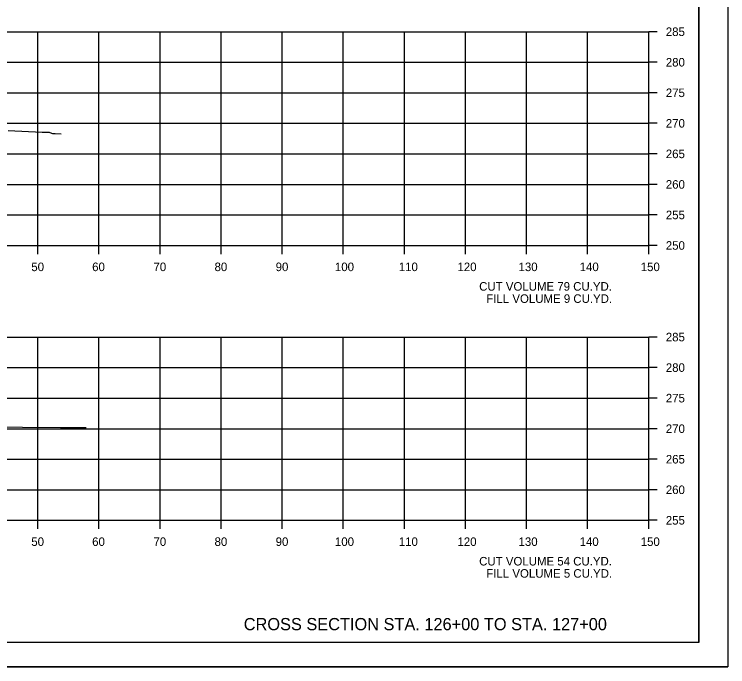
# Model space of a CAD drawing. Extents: x 1103485 to 1107180, y 2010593 to 2011873.
# Drawn here: x 1107063.3 to 1107180.1, y 2010806.2 to 2010913 of the extents above; entities that cross this region are included whole.
import ezdxf

# ---------------------------------------------------------------- set-up
doc = ezdxf.new("R2010")
doc.units = 0
for name, color, linetype in [('R_Axis', 7, 'Continuous'), ('R_Axis Annot', 7, 'Continuous'), ('R_Border', 7, 'Continuous'), ('R_Draft', 7, 'Continuous'), ('R_Exist Surface', 7, 'Continuous'), ('R_Grid', 7, 'Continuous'), ('R_No Plot', 7, 'Continuous')]:
    doc.layers.add(name, color=color, linetype=linetype)

msp = doc.modelspace()

# ---------------------------------------------------------------- linework, layer by layer
at = {"layer": 'R_Axis'}
for p, q in [((1107167.18, 2010875.15), (1107167.18, 2010910.15)), ((1107168.58, 2010910.15), (1107167.18, 2010910.15)), ((1107168.58, 2010905.15), (1107167.18, 2010905.15)), ((1107168.58, 2010900.15), (1107167.18, 2010900.15)), ((1107168.58, 2010895.15), (1107167.18, 2010895.15)), ((1107168.58, 2010890.15), (1107167.18, 2010890.15)), ((1107168.58, 2010885.15), (1107167.18, 2010885.15)), ((1107168.58, 2010880.15), (1107167.18, 2010880.15)), ((1106867.18, 2010875.15), (1107167.18, 2010875.15)), ((1107067.18, 2010873.75), (1107067.18, 2010875.15)), ((1107077.18, 2010873.75), (1107077.18, 2010875.15)), ((1107087.18, 2010873.75), (1107087.18, 2010875.15)), ((1107097.18, 2010873.75), (1107097.18, 2010875.15)), ((1107107.18, 2010873.75), (1107107.18, 2010875.15)), ((1107117.18, 2010873.75), (1107117.18, 2010875.15)), ((1107127.18, 2010873.75), (1107127.18, 2010875.15)), ((1107137.18, 2010873.75), (1107137.18, 2010875.15)), ((1107147.18, 2010873.75), (1107147.18, 2010875.15)), ((1107157.18, 2010873.75), (1107157.18, 2010875.15)), ((1107167.18, 2010873.75), (1107167.18, 2010875.15)), ((1107168.58, 2010875.15), (1107167.18, 2010875.15)), ((1107167.18, 2010830.15), (1107167.18, 2010860.15)), ((1107168.58, 2010860.15), (1107167.18, 2010860.15)), ((1107168.58, 2010855.15), (1107167.18, 2010855.15)), ((1107168.58, 2010850.15), (1107167.18, 2010850.15)), ((1107168.58, 2010845.15), (1107167.18, 2010845.15)), ((1107168.58, 2010840.15), (1107167.18, 2010840.15)), ((1107168.58, 2010835.15), (1107167.18, 2010835.15)), ((1106867.18, 2010830.15), (1107167.18, 2010830.15)), ((1107067.18, 2010828.75), (1107067.18, 2010830.15)), ((1107077.18, 2010828.75), (1107077.18, 2010830.15)), ((1107087.18, 2010828.75), (1107087.18, 2010830.15)), ((1107097.18, 2010828.75), (1107097.18, 2010830.15)), ((1107107.18, 2010828.75), (1107107.18, 2010830.15)), ((1107117.18, 2010828.75), (1107117.18, 2010830.15)), ((1107127.18, 2010828.75), (1107127.18, 2010830.15)), ((1107137.18, 2010828.75), (1107137.18, 2010830.15)), ((1107147.18, 2010828.75), (1107147.18, 2010830.15)), ((1107157.18, 2010828.75), (1107157.18, 2010830.15)), ((1107167.18, 2010828.75), (1107167.18, 2010830.15)), ((1107168.58, 2010830.15), (1107167.18, 2010830.15))]:
    msp.add_line(p, q, dxfattribs=at)
at = {"layer": 'R_Border'}
for q in [(1107175.36, 2011015.61), (1106859.18, 2010810.15)]:
    msp.add_line((1107175.36, 2010810.15), q, dxfattribs=at)
at = {"layer": 'R_Exist Surface'}
for points in [[(1107062.32, 2010893.97), (1107067.87, 2010893.72), (1107069.01, 2010893.69), (1107069.14, 2010893.64), (1107069.56, 2010893.46), (1107070.02, 2010893.51), (1107070.98, 2010893.42)], [(1107052.24, 2010845.53), (1107070.89, 2010845.37), (1107074.81, 2010845.33), (1107075.06, 2010845.32)]]:
    msp.add_lwpolyline(points, dxfattribs=at)
at = {"layer": 'R_Grid'}
for p, q in [((1106867.18, 2010910.15), (1107167.18, 2010910.15)), ((1107067.18, 2010875.15), (1107067.18, 2010910.15)), ((1107077.18, 2010875.15), (1107077.18, 2010910.15)), ((1107087.18, 2010875.15), (1107087.18, 2010910.15)), ((1107097.18, 2010875.15), (1107097.18, 2010910.15)), ((1107107.18, 2010875.15), (1107107.18, 2010910.15)), ((1107117.18, 2010875.15), (1107117.18, 2010910.15)), ((1107127.18, 2010875.15), (1107127.18, 2010910.15)), ((1107137.18, 2010875.15), (1107137.18, 2010910.15)), ((1107147.18, 2010875.15), (1107147.18, 2010910.15)), ((1107157.18, 2010875.15), (1107157.18, 2010910.15)), ((1107167.18, 2010875.15), (1107167.18, 2010910.15)), ((1106867.18, 2010905.15), (1107167.18, 2010905.15)), ((1106867.18, 2010900.15), (1107167.18, 2010900.15)), ((1106867.18, 2010895.15), (1107167.18, 2010895.15)), ((1106867.18, 2010890.15), (1107167.18, 2010890.15)), ((1106867.18, 2010885.15), (1107167.18, 2010885.15)), ((1106867.18, 2010880.15), (1107167.18, 2010880.15)), ((1106867.18, 2010875.15), (1107167.18, 2010875.15)), ((1106867.18, 2010860.15), (1107167.18, 2010860.15)), ((1107067.18, 2010830.15), (1107067.18, 2010860.15)), ((1107077.18, 2010830.15), (1107077.18, 2010860.15)), ((1107087.18, 2010830.15), (1107087.18, 2010860.15)), ((1107097.18, 2010830.15), (1107097.18, 2010860.15)), ((1107107.18, 2010830.15), (1107107.18, 2010860.15)), ((1107117.18, 2010830.15), (1107117.18, 2010860.15)), ((1107127.18, 2010830.15), (1107127.18, 2010860.15)), ((1107137.18, 2010830.15), (1107137.18, 2010860.15)), ((1107147.18, 2010830.15), (1107147.18, 2010860.15)), ((1107157.18, 2010830.15), (1107157.18, 2010860.15)), ((1107167.18, 2010830.15), (1107167.18, 2010860.15)), ((1106867.18, 2010855.15), (1107167.18, 2010855.15)), ((1106867.18, 2010850.15), (1107167.18, 2010850.15)), ((1106867.18, 2010845.15), (1107167.18, 2010845.15)), ((1106867.18, 2010840.15), (1107167.18, 2010840.15)), ((1106867.18, 2010835.15), (1107167.18, 2010835.15)), ((1106867.18, 2010830.15), (1107167.18, 2010830.15))]:
    msp.add_line(p, q, dxfattribs=at)
at = {"layer": 'R_No Plot'}
msp.add_line((1106846.78, 2010806.18), (1107180.12, 2010806.18), dxfattribs=at)
for points in [[(1106846.78, 2011019.51), (1107180.12, 2011019.51), (1107180.12, 2010806.17), (1106846.78, 2010806.17)], [(1107093.1, 2011015.61), (1107093.1, 2011005.73), (1107128.84, 2011005.73), (1107128.84, 2011002.81), (1107152.04, 2011002.81), (1107152.04, 2010978.48), (1107175.36, 2010978.48), (1107175.36, 2010810.15), (1106859.18, 2010810.15), (1106859.18, 2011015.61)]]:
    msp.add_lwpolyline(points, close=True, dxfattribs=at)

# ---------------------------------------------------------------- texts
at = {"layer": 'R_Axis Annot'}
for s, p in [('285', (1107169.98, 2010909.45)), ('280', (1107169.98, 2010904.45)), ('275', (1107169.98, 2010899.45)), ('270', (1107169.98, 2010894.45)), ('265', (1107169.98, 2010889.45)), ('260', (1107169.98, 2010884.45)), ('255', (1107169.98, 2010879.45)), ('250', (1107169.98, 2010874.45)), ('50', (1107066.1, 2010870.95)), ('60', (1107076.06, 2010870.95)), ('70', (1107086.1, 2010870.95)), ('80', (1107096.1, 2010870.95)), ('90', (1107106.1, 2010870.95)), ('100', (1107115.81, 2010870.95)), ('110', (1107126.26, 2010870.95)), ('120', (1107135.87, 2010870.95)), ('130', (1107145.87, 2010870.95)), ('140', (1107155.87, 2010870.95)), ('150', (1107165.87, 2010870.95)), ('CUT VOLUME 79 CU.YD.', (1107139.42, 2010867.75)), ('FILL VOLUME 9 CU.YD.', (1107140.59, 2010865.75)), ('285', (1107169.98, 2010859.45)), ('280', (1107169.98, 2010854.45)), ('275', (1107169.98, 2010849.45)), ('270', (1107169.98, 2010844.45)), ('265', (1107169.98, 2010839.45)), ('260', (1107169.98, 2010834.45)), ('255', (1107169.98, 2010829.45)), ('50', (1107066.1, 2010825.95)), ('60', (1107076.06, 2010825.95)), ('70', (1107086.1, 2010825.95)), ('80', (1107096.1, 2010825.95)), ('90', (1107106.1, 2010825.95)), ('100', (1107115.81, 2010825.95)), ('110', (1107126.26, 2010825.95)), ('120', (1107135.87, 2010825.95)), ('130', (1107145.87, 2010825.95)), ('140', (1107155.87, 2010825.95)), ('150', (1107165.87, 2010825.95)), ('CUT VOLUME 54 CU.YD.', (1107139.42, 2010822.75)), ('FILL VOLUME 5 CU.YD.', (1107140.59, 2010820.75))]:
    msp.add_text(s, height=1.4, dxfattribs=at).set_placement(p)
at = {"layer": 'R_Draft'}
msp.add_text('CROSS SECTION STA. 126+00 TO STA. 127+00', height=2, dxfattribs=at).set_placement((1107100.88, 2010812.15))

doc.saveas('drawing.dxf')
